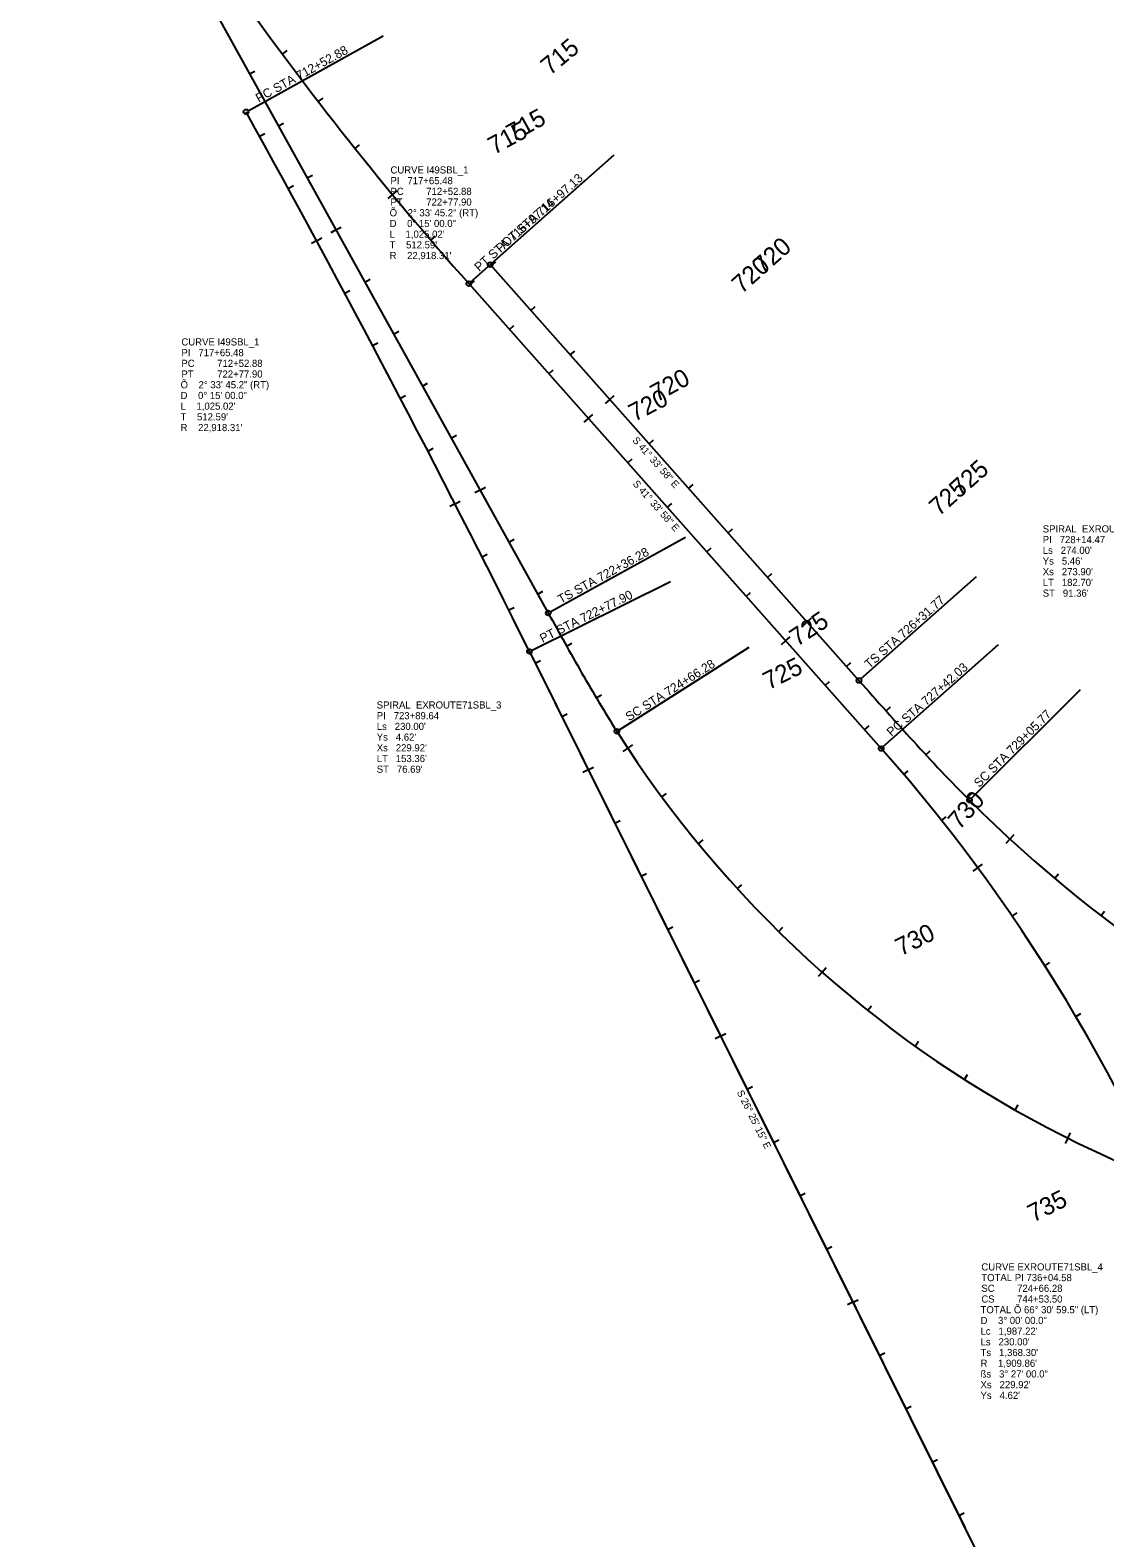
# Model space of a CAD drawing. Extents: x 2819977 to 2827606, y 116785 to 150320.
# Drawn here: x 2821676 to 2823483, y 144853 to 147388 of the extents above; entities that cross this region are included whole.
import ezdxf

# ---------------------------------------------------------------- set-up
doc = ezdxf.new("R2010")
doc.units = 0
for name, color, linetype in [('Default', 7, 'Continuous'), ('Modeling-Contours-Major-Existing', 7, 'Continuous'), ('Modeling-Contours-Minor-Existing', 7, 'Continuous'), ('Modeling-Flow Arrows-Existing', 7, 'Continuous'), ('Modeling-Spot-Existing', 7, 'Continuous'), ('Modeling-Triangle Verticies-Existing', 7, 'Continuous')]:
    doc.layers.add(name, color=color, linetype=linetype)

msp = doc.modelspace()

# ---------------------------------------------------------------- linework, layer by layer
at = {"layer": 'Default'}
for p, q in [((2822413.7, 146961.8), (2823107, 146180)), ((2822413.7, 146961.8), (2823107, 146180)), ((2822515.7, 146343.3), (2823322.4, 144719.6)), ((2822515.7, 146343.3), (2823247.6, 144870.2))]:
    msp.add_line(p, q, dxfattribs=at)
for centre, radius, start, end in [((2824274.6, 147233.3), 1909.9, 212.4335, 272.05), ((2820963.6, 144279.3), 2864.8, 356.8489, 41.5661), ((2824876.4, 147713.4), 2291.8, 224.9911, 272.075)]:
    msp.add_arc(centre, radius, start, end, dxfattribs=at)
for points in [[(2822547.2, 146407.9), (2822556.5, 146391.1), (2822575, 146357.6), (2822603.3, 146307.5), (2822632.3, 146257.9), (2822652.4, 146225.2), (2822662.6, 146209)], [(2823069.7, 146294.4), (2823084.9, 146277.3), (2823115.2, 146243.1), (2823161, 146192.2), (2823207.6, 146142), (2823239.4, 146109.2), (2823255.5, 146093.1)]]:
    msp.add_open_spline(points, degree=3, dxfattribs=at)
at = {"layer": 'Modeling-Contours-Major-Existing'}
for p, q in [((2821676.3, 147980.2), (2822547.2, 146407.9)), ((2822045.1, 147314.4), (2822053.8, 147319.3)), ((2822093.5, 147226.9), (2822102.3, 147231.8)), ((2822142, 147139.5), (2822150.7, 147144.3)), ((2822190.4, 147052), (2822181.7, 147047.1)), ((2822190.4, 147052), (2822199.2, 147056.8)), ((2822451.5, 146991.5), (2822459, 146998.2)), ((2822449.6, 146993.7), (2823069.7, 146294.4)), ((2822238.9, 146964.5), (2822247.6, 146969.3)), ((2822517.9, 146916.7), (2822525.3, 146923.3)), ((2822287.3, 146877), (2822296.1, 146881.9)), ((2822584.2, 146841.9), (2822591.7, 146848.5)), ((2822335.8, 146789.5), (2822344.5, 146794.4)), ((2822650.6, 146767.1), (2822643.1, 146760.4)), ((2822650.6, 146767.1), (2822658, 146773.7)), ((2822384.3, 146702.1), (2822393, 146706.9)), ((2822716.9, 146692.2), (2822724.4, 146698.9)), ((2822432.7, 146614.6), (2822441.5, 146619.4)), ((2822783.2, 146617.4), (2822790.7, 146624.1)), ((2822432.7, 146614.6), (2822424, 146609.8)), ((2822849.6, 146542.6), (2822857.1, 146549.2)), ((2822481.2, 146527.1), (2822489.9, 146532)), ((2822915.9, 146467.8), (2822923.4, 146474.4)), ((2822529.6, 146439.6), (2822538.4, 146444.5)), ((2822982.3, 146393), (2822974.8, 146386.3)), ((2822982.3, 146393), (2822989.8, 146399.6)), ((2822578.2, 146352.2), (2822586.9, 146357.1)), ((2823048.6, 146318.1), (2823056.1, 146324.8)), ((2822628, 146265.5), (2822636.6, 146270.6)), ((2823115.1, 146243.4), (2823122.5, 146250)), ((2822681, 146180.7), (2822689.3, 146186.2)), ((2822681, 146180.7), (2822672.6, 146175.2)), ((2823182.3, 146169.4), (2823189.6, 146176.2)), ((2822738.3, 146098.8), (2822746.3, 146104.7)), ((2823251.5, 146097.2), (2823258.6, 146104.2)), ((2823323.5, 146027.8), (2823330.3, 146035.2)), ((2822799.7, 146019.9), (2822807.5, 146026.3)), ((2823323.5, 146027.8), (2823316.7, 146020.5)), ((2823398.5, 145961.7), (2823405, 145969.3)), ((2822865.3, 145944.4), (2822872.6, 145951.1)), ((2823476.3, 145898.9), (2823482.4, 145906.8)), ((2822934.7, 145872.4), (2822941.7, 145879.5)), ((2823007.7, 145804.1), (2823001.1, 145796.6)), ((2823007.7, 145804.1), (2823014.3, 145811.6)), ((2823084.2, 145739.8), (2823090.5, 145747.6)), ((2823164, 145679.5), (2823169.9, 145687.7)), ((2823246.9, 145623.5), (2823252.3, 145632)), ((2823332.5, 145572), (2823337.5, 145580.7)), ((2823420.8, 145524.9), (2823416.3, 145516)), ((2823420.8, 145524.9), (2823425.3, 145533.9))]:
    msp.add_line(p, q, dxfattribs=at)
for centre, radius, start, end in [((2824274.6, 147233.3), 1909.9, 212.4335, 272.05), ((2824876.4, 147713.4), 2291.8, 224.9911, 272.075)]:
    msp.add_arc(centre, radius, start, end, dxfattribs=at)
for points in [[(2822547.2, 146407.9), (2822556.5, 146391.1), (2822575, 146357.6), (2822603.3, 146307.5), (2822632.3, 146257.9), (2822652.4, 146225.2), (2822662.6, 146209)], [(2823069.7, 146294.4), (2823084.9, 146277.3), (2823115.2, 146243.1), (2823161, 146192.2), (2823207.6, 146142), (2823239.4, 146109.2), (2823255.5, 146093.1)]]:
    msp.add_open_spline(points, degree=3, dxfattribs=at)
at = {"layer": 'Modeling-Contours-Minor-Existing'}
for p, q in [((2822452.6, 146996.3), (2822658.2, 147178.6)), ((2822550.7, 146409.8), (2822777.9, 146535.7)), ((2823072.7, 146297), (2823267.1, 146469.4)), ((2822666, 146211.2), (2822885.3, 146350.5)), ((2823258.4, 146095.9), (2823442.1, 146279.5))]:
    msp.add_line(p, q, dxfattribs=at)
for centre in [(2822449.6, 146993.7), (2822547.2, 146407.9), (2823069.7, 146294.4), (2822662.6, 146209), (2823255.5, 146093.1)]:
    msp.add_circle(centre, 4, dxfattribs=at)
at = {"layer": 'Modeling-Flow Arrows-Existing'}
for p, q in [((2822100.4, 147347.6), (2822108.4, 147353.6)), ((2822160.7, 147267.8), (2822168.6, 147273.9)), ((2822062, 147209.5), (2822070.7, 147214.3)), ((2822222.4, 147189.1), (2822230.2, 147195.4)), ((2822110.1, 147121.8), (2822118.9, 147126.6)), ((2822285.5, 147111.5), (2822277.7, 147105.2)), ((2822285.5, 147111.5), (2822293.2, 147117.9)), ((2822157.8, 147033.9), (2822149, 147029.1)), ((2822157.8, 147033.9), (2822166.6, 147038.6)), ((2822349.9, 147035), (2822357.5, 147041.5)), ((2822205.1, 146945.8), (2822213.9, 146950.5)), ((2822413.7, 146961.8), (2823107, 146180)), ((2822415.6, 146959.7), (2822423.1, 146966.3)), ((2822481.9, 146884.9), (2822489.4, 146891.5)), ((2822252, 146857.5), (2822260.9, 146862.2)), ((2822548.3, 146810), (2822555.8, 146816.7)), ((2822298.6, 146769), (2822307.4, 146773.6)), ((2822614.6, 146735.2), (2822622.1, 146741.9)), ((2822614.6, 146735.2), (2822607.2, 146728.6)), ((2822344.7, 146680.3), (2822353.6, 146684.9)), ((2822681, 146660.4), (2822688.5, 146667)), ((2822390.5, 146591.4), (2822381.6, 146586.8)), ((2822390.5, 146591.4), (2822399.4, 146595.9)), ((2822747.3, 146585.6), (2822754.8, 146592.2)), ((2822813.7, 146510.8), (2822821.2, 146517.4)), ((2822435.9, 146502.3), (2822444.8, 146506.8)), ((2822880, 146435.9), (2822887.5, 146442.6)), ((2822480.9, 146413), (2822489.8, 146417.4)), ((2822946.4, 146361.1), (2822953.9, 146367.8)), ((2822515.7, 146343.3), (2823322.4, 144719.6)), ((2822946.4, 146361.1), (2822938.9, 146354.5)), ((2822525.5, 146323.5), (2822534.5, 146327.9)), ((2823012.7, 146286.3), (2823020.2, 146292.9)), ((2822570, 146233.9), (2822578.9, 146238.4)), ((2823079.1, 146211.5), (2823086.6, 146218.1)), ((2822614.5, 146144.3), (2822605.5, 146139.9)), ((2822614.5, 146144.3), (2822623.4, 146148.8)), ((2823145, 146136.3), (2823152.6, 146142.8)), ((2822659, 146054.8), (2822667.9, 146059.2)), ((2823208.5, 146059), (2823216.3, 146065.2)), ((2823269.2, 145979.6), (2823277.3, 145985.5)), ((2822703.5, 145965.2), (2822712.4, 145969.7)), ((2823269.2, 145979.6), (2823261.2, 145973.7)), ((2822748, 145875.7), (2822756.9, 145880.1)), ((2823327.1, 145898.1), (2823335.4, 145903.7)), ((2823382.2, 145814.6), (2823390.6, 145820)), ((2822792.5, 145786.1), (2822801.4, 145790.6)), ((2823434.3, 145729.3), (2823442.9, 145734.3)), ((2822837, 145696.6), (2822828, 145692.1)), ((2822837, 145696.6), (2822845.9, 145701)), ((2822881.5, 145607), (2822890.4, 145611.5)), ((2822926, 145517.5), (2822934.9, 145521.9)), ((2822970.5, 145427.9), (2822979.4, 145432.4)), ((2823015, 145338.4), (2823023.9, 145342.8)), ((2823059.5, 145248.8), (2823050.5, 145244.4)), ((2823059.5, 145248.8), (2823068.4, 145253.2)), ((2823103.9, 145159.2), (2823112.9, 145163.7)), ((2823148.4, 145069.7), (2823157.4, 145074.1)), ((2823192.9, 144980.1), (2823201.9, 144984.6)), ((2823237.4, 144890.6), (2823246.4, 144895))]:
    msp.add_line(p, q, dxfattribs=at)
for centre, radius, start, end in [((2826700.5, 150763.3), 5729.6, 208.98347, 221.56614), ((2801991.2, 136145.5), 22918.3, 26.42092, 28.98346), ((2820963.6, 144279.3), 2864.8, 356.8489, 41.5661)]:
    msp.add_arc(centre, radius, start, end, dxfattribs=at)
at = {"layer": 'Modeling-Spot-Existing'}
for p, q in [((2822042.7, 147252.6), (2822269.9, 147378.5)), ((2822416.7, 146964.5), (2822611, 147136.8)), ((2822519.2, 146345), (2822752.9, 146461.1)), ((2823110, 146182.7), (2823304.3, 146355))]:
    msp.add_line(p, q, dxfattribs=at)
for centre in [(2822039.2, 147250.7), (2822413.7, 146961.8), (2822515.7, 146343.3), (2823107, 146180)]:
    msp.add_circle(centre, 4, dxfattribs=at)

# ---------------------------------------------------------------- texts
at = {"layer": 'Modeling-Contours-Major-Existing'}
for s, rotation, p in [(' 715', 28.9835, (2822477.6, 147193.9)), (' 720', 41.5661, (2822899.9, 146968.2)), (' 720', 28.9835, (2822719.9, 146756.5)), (' 725', 41.5661, (2823231.7, 146594.1)), (' 725', 33.445, (2822956.3, 146344.6)), (' 730', 48.445, (2823231.2, 146033.6))]:
    msp.add_text(s, height=30, rotation=rotation, dxfattribs=at).set_placement(p)
at = {"layer": 'Modeling-Contours-Minor-Existing'}
for s, height, rotation, p in [('POT STA 716+97.13', 15, 41.5661, (2822467.1, 147013.2)), ('S 41%%d 33\' 58" E', 12, 311.5661, (2822688, 146697.7)), ('S 41%%d 33\' 58" E', 12, 311.5661, (2822688.6, 146624.6)), ('TS STA 722+36.28', 15, 28.9835, (2822568.5, 146423.1)), ('TS STA 726+31.77', 15, 41.5661, (2823087.2, 146313.9)), ('SC STA 724+66.28', 15, 32.4335, (2822683, 146225.5)), ('SC STA 729+05.77', 15, 44.9911, (2823271.8, 146113.6)), ('S 26%%d 25\' 15" E', 12, 296.4209, (2822863.9, 145602))]:
    msp.add_text(s, height=height, rotation=rotation, dxfattribs=at).set_placement(p)
at = {"layer": 'Modeling-Flow Arrows-Existing'}
for s, rotation, p in [(' 715', 39.5948, (2822541.6, 147303.9)), (' 715', 28.3657, (2822446.5, 147172.7)), (' 720', 41.5661, (2822864, 146936.3)), (' 720', 27.1157, (2822682.2, 146723.9)), (' 725', 41.5661, (2823195.7, 146562.2)), (' 725', 26.4209, (2822907.7, 146273.3)), (' 730', 26.4209, (2823130.2, 145825.5)), (' 735', 26.4209, (2823352.7, 145377.8))]:
    msp.add_text(s, height=30, rotation=rotation, dxfattribs=at).set_placement(p)
at = {"layer": 'Modeling-Spot-Existing'}
for s, rotation, p in [('PC STA 712+52.88', 28.9835, (2822060.5, 147265.9)), ('PT STA 716+97.14', 41.5661, (2822431.2, 146981.3)), ('PT STA 722+77.90', 26.4209, (2822537.6, 146357.5)), ('PC STA 727+42.03', 41.5661, (2823124.4, 146199.5))]:
    msp.add_text(s, height=15, rotation=rotation, dxfattribs=at).set_placement(p)
at = {"layer": 'Modeling-Triangle Verticies-Existing'}
for s, p in [('CURVE I49SBL_1', (2822282, 147147)), ('PI   717+65.48', (2822282, 147129)), ('PC', (2822282, 147111)), ('712+52.88', (2822342.2, 147111)), ('PT', (2822282, 147093)), ('722+77.90', (2822342.2, 147093)), ('Õ    2%%d 33\' 45.2" (RT)', (2822280.6, 147075)), ('D    0%%d 15\' 00.0"', (2822280.6, 147057)), ("L    1,025.02'", (2822280.6, 147039)), ("T    512.59'", (2822280.6, 147021)), ("R    22,918.31'", (2822280.6, 147003)), ('CURVE I49SBL_1', (2821930.5, 146857.8)), ('PI   717+65.48', (2821930.5, 146839.8)), ('PC', (2821930.5, 146821.8)), ('712+52.88', (2821990.7, 146821.8)), ('Õ    2%%d 33\' 45.2" (RT)', (2821929.1, 146785.8)), ('PT', (2821930.5, 146803.8)), ('722+77.90', (2821990.7, 146803.8)), ('D    0%%d 15\' 00.0"', (2821929.1, 146767.8)), ("T    512.59'", (2821929.1, 146731.8)), ("L    1,025.02'", (2821929.1, 146749.8)), ("R    22,918.31'", (2821929.1, 146713.8)), ('SPIRAL  EXROUTE71NBL_3', (2823378.6, 146543.4)), ('PI   728+14.47', (2823378.6, 146525.4)), ("Ls   274.00'", (2823378.6, 146507.4)), ("Ys   5.46'", (2823378.6, 146489.4)), ("Xs   273.90'", (2823378.6, 146471.4)), ("LT   182.70'", (2823378.6, 146453.4)), ("ST   91.36'", (2823378.6, 146435.4)), ('SPIRAL  EXROUTE71SBL_3', (2822258.9, 146247.3)), ('PI   723+89.64', (2822258.9, 146229.3)), ("Ls   230.00'", (2822258.9, 146211.3)), ("Ys   4.62'", (2822258.9, 146193.3)), ("Xs   229.92'", (2822258.9, 146175.3)), ("LT   153.36'", (2822258.9, 146157.3)), ("ST   76.69'", (2822258.9, 146139.3)), ('TOTAL PI 736+04.58', (2823275.4, 145284.4)), ('CURVE EXROUTE71SBL_4', (2823275.4, 145302.4)), ('SC', (2823275.4, 145266.4)), ('724+66.28', (2823335.5, 145266.4)), ('CS', (2823275.4, 145248.4)), ('744+53.50', (2823335.5, 145248.4)), ('TOTAL Õ 66%%d 30\' 59.5" (LT)', (2823274, 145230.4)), ('D    3%%d 00\' 00.0"', (2823274, 145212.4)), ("Lc   1,987.22'", (2823274, 145194.4)), ("Ts   1,368.30'", (2823274, 145158.4)), ("Ls   230.00'", (2823274, 145176.4)), ("R    1,909.86'", (2823274, 145140.4)), ('ßs   3%%d 27\' 00.0"', (2823274, 145122.4)), ("Xs   229.92'", (2823274, 145104.4)), ("Ys   4.62'", (2823274, 145086.4))]:
    msp.add_text(s, height=12, dxfattribs=at).set_placement(p)

doc.saveas('drawing.dxf')
